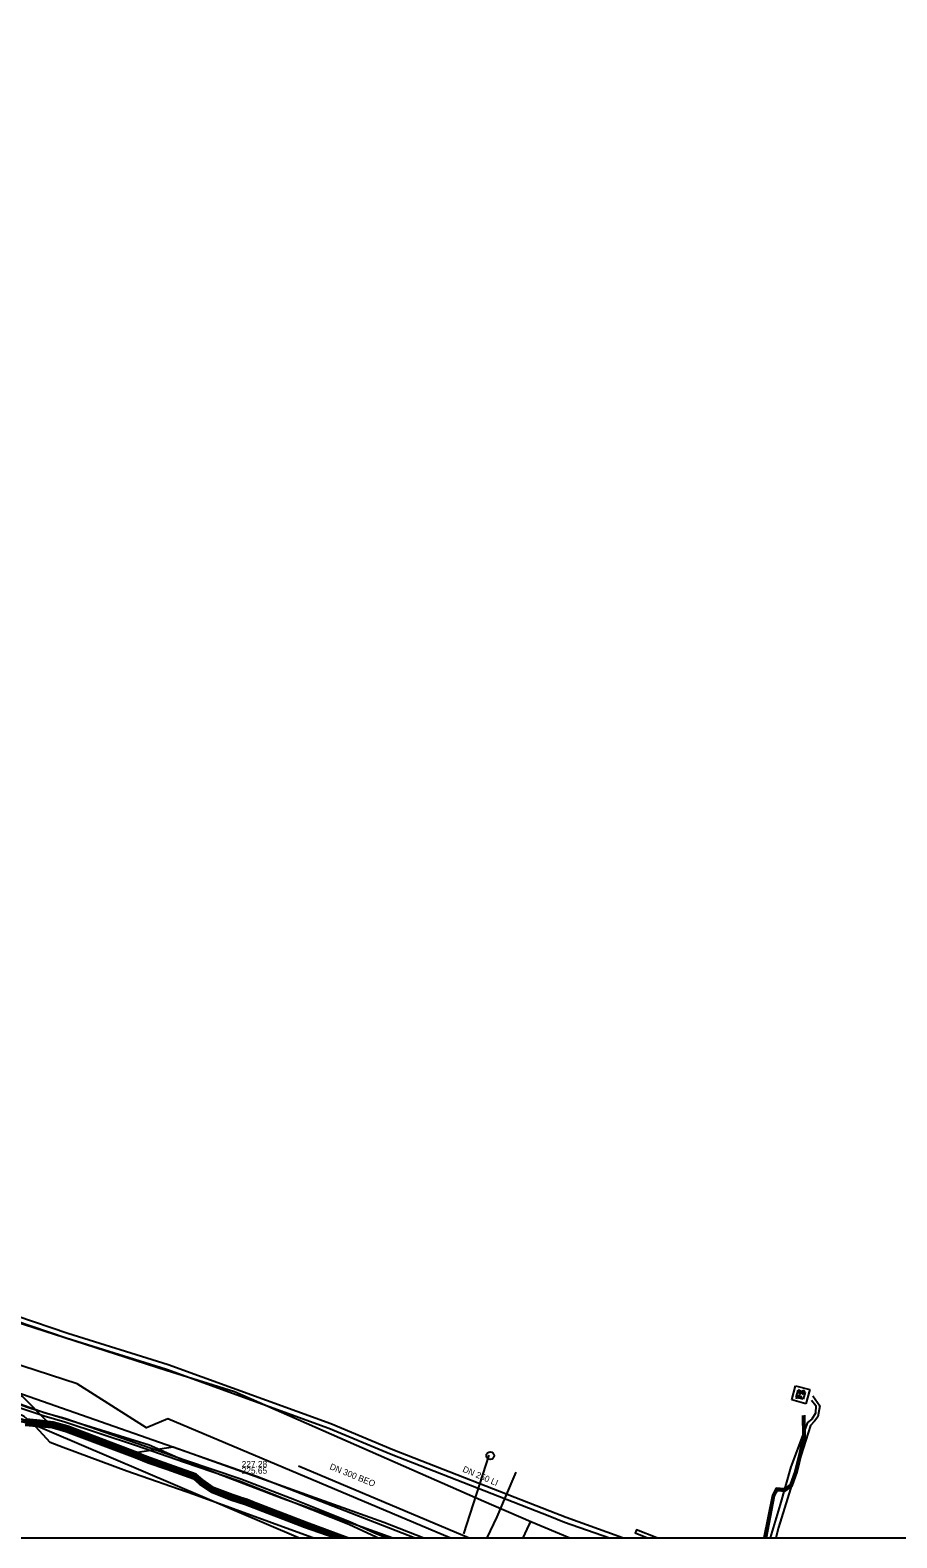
# Model space of a CAD drawing. Extents: x -599951 to -598963, y -1164095 to -1162939.
# Drawn here: x -599566.7 to -599455.4, y -1164094.7 to -1163901.1 of the extents above; entities that cross this region are included whole.
import ezdxf

# ---------------------------------------------------------------- set-up
doc = ezdxf.new("R2010")
doc.units = 0
for name, color, linetype in [('25', 7, 'Continuous'), ('Vrstva 11', 7, 'Continuous'), ('Vrstva 12', 7, 'Continuous'), ('Vrstva 13', 7, 'Continuous'), ('Vrstva 15', 7, 'Continuous'), ('Vrstva 16', 7, 'Continuous'), ('Vrstva 19', 7, 'Continuous'), ('Vrstva 3', 7, 'Continuous'), ('Vrstva 42', 7, 'Continuous'), ('Vrstva 43', 7, 'Continuous'), ('Vrstva 44', 7, 'Continuous'), ('Vrstva 45', 7, 'Continuous'), ('Vrstva 53', 7, 'Continuous'), ('Vrstva 55', 7, 'Continuous'), ('Vrstva 58', 7, 'Continuous'), ('Vrstva 9', 7, 'Continuous')]:
    doc.layers.add(name, color=color, linetype=linetype)

# ---------------------------------------------------------------- blocks, each defined once
blk = doc.blocks.new('VN640')
at = {"layer": '25'}
for points in [[(-1.89, 1.889), (1.889, 1.889)], [(-1.89, -1.89), (-1.89, 1.889)], [(-1.26, 0.787), (-0.221, 0.787)], [(-0.725, 0.787), (-0.725, -0.788)], [(1.197, 0.661), (0.945, 0.787), (0.661, 0.787), (0.409, 0.661), (0.283, 0.472), (0.283, 0.409), (0.409, 0.22), (1.133, -0.158), (1.259, -0.316), (1.259, -0.473), (1.133, -0.662), (0.913, -0.788), (0.629, -0.788), (0.503, -0.725), (0.283, -0.599)], [(1.889, 1.889), (1.889, -1.89)], [(1.889, -1.89), (-1.89, -1.89)]]:
    blk.add_lwpolyline(points, dxfattribs=at)
blk = doc.blocks.new('NN640')
at = {"layer": '25'}
for points in [[(-1.89, 1.889), (1.889, 1.889)], [(-1.89, -1.89), (-1.89, 1.889)], [(-1.26, 0.787), (-0.221, 0.787)], [(-0.725, 0.787), (-0.725, -0.788)], [(1.197, 0.661), (0.945, 0.787), (0.661, 0.787), (0.409, 0.661), (0.283, 0.472), (0.283, 0.409), (0.409, 0.22), (1.133, -0.158), (1.259, -0.316), (1.259, -0.473), (1.133, -0.662), (0.913, -0.788), (0.629, -0.788), (0.503, -0.725), (0.283, -0.599)], [(1.889, 1.889), (1.889, -1.89)], [(1.889, -1.89), (-1.89, -1.89)]]:
    blk.add_lwpolyline(points, dxfattribs=at)

msp = doc.modelspace()

# ---------------------------------------------------------------- linework, layer by layer
at = {"layer": 'Vrstva 11'}
msp.add_circle((-599507.63, -1164084.14), 0.5, dxfattribs=at)
at = {"layer": 'Vrstva 12'}
for points in [[(-599613.46, -1164062.85), (-599613.16, -1164063.2), (-599611.72, -1164063.65), (-599602.03, -1164066.71), (-599599.57, -1164067.42), (-599595.65, -1164068.31), (-599580.24, -1164073.43), (-599577.04, -1164074.47), (-599566.64, -1164078.04), (-599562.59, -1164079.3), (-599551.43, -1164082.77), (-599546.18, -1164085.05), (-599534.35, -1164089.62), (-599520.153, -1164094.695)], [(-599512.817, -1164094.695), (-599549.011, -1164079.426), (-599551.753, -1164080.567), (-599560.66, -1164074.929), (-599578.175, -1164069.238), (-599581.79, -1164068.099), (-599587.439, -1164066.331), (-599595.493, -1164065.607), (-599599.144, -1164064.549), (-599601.105, -1164063.983), (-599607.16, -1164088.185), (-599608.496, -1164094.695)], [(-599565.95, -1164080.45), (-599567.47, -1164079.13), (-599569.21, -1164078.29), (-599577.43, -1164075.58), (-599580.28, -1164074.63), (-599581.54, -1164074.23)], [(-599530.396, -1164094.695), (-599531, -1164094.48), (-599545.67, -1164089.14), (-599554.28, -1164086.13), (-599562.44, -1164083.09), (-599564.11, -1164082.45), (-599565.95, -1164080.45)]]:
    msp.add_lwpolyline(points, dxfattribs=at)
at = {"layer": 'Vrstva 13'}
for points in [[(-599607.67, -1164054.96), (-599590.92, -1164059.94), (-599589.853, -1164060.27), (-599573.8, -1164065.2), (-599570.07, -1164066.42), (-599549.24, -1164073.15), (-599540.472, -1164075.88), (-599508.435, -1164089.969), (-599502.44, -1164092.61), (-599497.429, -1164094.695)], [(-599502.44, -1164092.61), (-599502.68, -1164093.04), (-599503.463, -1164094.695)]]:
    msp.add_lwpolyline(points, dxfattribs=at)
at = {"layer": 'Vrstva 16'}
msp.add_lwpolyline([(-599532.23, -1164094.695), (-599576.26, -1164075.92), (-599581.33, -1164074.29), (-599595.84, -1164069.64), (-599596.96, -1164069.28), (-599602.44, -1164067.76), (-599618.73, -1164062.85), (-599666.38, -1164048.5), (-599672.28, -1164046.86), (-599687.99, -1164042.5)], dxfattribs=at)
at = {"layer": 'Vrstva 19'}
for points in [[(-599517.408, -1164094.695), (-599537.5, -1164086.87), (-599571.84, -1164074.84), (-599589.93, -1164069.71), (-599590.38, -1164069.57), (-599590.89, -1164069.41), (-599601.93, -1164066.13), (-599608.97, -1164063.96), (-599646.01, -1164052.54), (-599646.71, -1164052.33), (-599646.97, -1164052.25), (-599649.244, -1164051.504), (-599665.68, -1164046.42), (-599687.59, -1164039.86)], [(-599508.01, -1164094.695), (-599506.76, -1164092), (-599505.665, -1164089.453), (-599504.3, -1164086.28)]]:
    msp.add_lwpolyline(points, dxfattribs=at)
at = {"layer": 'Vrstva 3'}
for points in [[(-599492.33, -1164094.695), (-599491.183, -1164094.695), (-599491.12, -1164094.53), (-599497.905, -1164092.099), (-599500, -1164091.28), (-599520.117, -1164083.412), (-599528.111, -1164080.071), (-599548.984, -1164072.466), (-599561.867, -1164068.455), (-599581.544, -1164061.776), (-599581.64, -1164062.06), (-599581.735, -1164062.342), (-599562.053, -1164069.025), (-599549.176, -1164073.034), (-599528.329, -1164080.629), (-599520.343, -1164083.968), (-599500, -1164091.924), (-599498.115, -1164092.661)], [(-599491.183, -1164094.695), (-599490.673, -1164094.695), (-599491.12, -1164094.53)], [(-599487.453, -1164094.695), (-599486.245, -1164094.695), (-599488.846, -1164093.651), (-599488.93, -1164093.86), (-599489.01, -1164094.07)]]:
    msp.add_lwpolyline(points, close=True, dxfattribs=at)
at = {"layer": 'Vrstva 42'}
for points in [[(-599526.966, -1164094.695), (-599531.336, -1164093.093), (-599538.889, -1164089.976), (-599543.516, -1164088.57), (-599545.077, -1164087.383), (-599546.233, -1164086.671), (-599549.427, -1164085.563), (-599553.029, -1164083.932), (-599561.911, -1164080.525), (-599563.749, -1164080.019), (-599565.43, -1164079.839), (-599567.196, -1164079.669)], [(-599526.386, -1164094.695), (-599531.264, -1164092.907), (-599538.831, -1164089.784), (-599543.424, -1164088.39), (-599544.963, -1164087.217), (-599546.147, -1164086.489), (-599549.353, -1164085.377), (-599552.951, -1164083.748), (-599561.849, -1164080.335), (-599563.711, -1164079.821), (-599565.41, -1164079.64), (-599567.164, -1164079.471)]]:
    msp.add_lwpolyline(points, dxfattribs=at)
at = {"layer": 'Vrstva 44'}
for points in [[(-599548.889, -1164085.258), (-599551.295, -1164084.429), (-599552.972, -1164083.76), (-599561.884, -1164080.426), (-599563.723, -1164079.874), (-599567.224, -1164079.573), (-599569.544, -1164079.052), (-599572.083, -1164078.09), (-599575.977, -1164076.588), (-599581.178, -1164074.784), (-599584.429, -1164073.814), (-599594.158, -1164070.534), (-599594.617, -1164070.415), (-599595.31, -1164069.65), (-599595.524, -1164069.061), (-599595.504, -1164068.88), (-599595.044, -1164067.4)], [(-599520.995, -1164094.695), (-599522.17, -1164094.21), (-599525.69, -1164092.63), (-599532.76, -1164089.83), (-599539.63, -1164087.15), (-599546.86, -1164084.73), (-599552.99, -1164082.57), (-599562.25, -1164079.36), (-599564.77, -1164078.7), (-599569.35, -1164077.07), (-599576.12, -1164075.03), (-599582.45, -1164072.98), (-599589.38, -1164070.73), (-599593.46, -1164069.48), (-599593.99, -1164069.3)], [(-599594.25, -1164070.82), (-599584.52, -1164074.1), (-599581.27, -1164075.07), (-599576.08, -1164076.87), (-599572.19, -1164078.37), (-599569.63, -1164079.34), (-599567.27, -1164079.87), (-599563.78, -1164080.17), (-599561.98, -1164080.71), (-599553.08, -1164084.04), (-599551.4, -1164084.71), (-599548.99, -1164085.54)], [(-599569.51, -1164077.47), (-599564.88, -1164079.03), (-599562.25, -1164079.78), (-599553.15, -1164082.78), (-599546.89, -1164084.97), (-599539.84, -1164087.37), (-599532.81, -1164090.15), (-599525.79, -1164092.95), (-599522.29, -1164094.58), (-599522.023, -1164094.695)], [(-599466.388, -1164077.007), (-599465.82, -1164077.71), (-599465.889, -1164078.694), (-599466.338, -1164079.45), (-599466.927, -1164079.898), (-599469.05, -1164085.58), (-599470.42, -1164090.41), (-599471.682, -1164094.695)], [(-599466.236, -1164076.474), (-599465.32, -1164077.72), (-599465.59, -1164079.15), (-599465.993, -1164079.709), (-599466.51, -1164080.26), (-599468.31, -1164085.93), (-599470.65, -1164093.35), (-599470.963, -1164094.695)], [(-599567.255, -1164079.771), (-599563.761, -1164080.071), (-599561.948, -1164080.615), (-599553.044, -1164083.947), (-599551.365, -1164084.616), (-599548.956, -1164085.446), (-599545.49, -1164086.712), (-599544.65, -1164087.39), (-599543.143, -1164088.441), (-599540.756, -1164089.366), (-599538.854, -1164089.987)], [(-599467.45, -1164078.961), (-599467.42, -1164081.661), (-599467.838, -1164083.748), (-599468.436, -1164086.191), (-599469.064, -1164087.918), (-599469.82, -1164088.488), (-599470.867, -1164088.416), (-599471.315, -1164089.246), (-599472.39, -1164094.695)], [(-599472.187, -1164094.695), (-599471.125, -1164089.314), (-599470.753, -1164088.624), (-599469.76, -1164088.692), (-599468.896, -1164088.042), (-599468.244, -1164086.249), (-599467.642, -1164083.792), (-599467.22, -1164081.679), (-599467.25, -1164078.959)], [(-599545.643, -1164087.082), (-599549.088, -1164085.824), (-599551.504, -1164084.991), (-599553.188, -1164084.32), (-599562.076, -1164080.994), (-599563.837, -1164080.466), (-599567.316, -1164080.167)], [(-599567.285, -1164079.969), (-599563.799, -1164080.269), (-599562.012, -1164080.805), (-599553.116, -1164084.133), (-599551.435, -1164084.804), (-599549.023, -1164085.635)], [(-599549.023, -1164085.635), (-599545.59, -1164086.888), (-599544.77, -1164087.55), (-599543.237, -1164088.619), (-599540.824, -1164089.554), (-599538.921, -1164090.175), (-599531.375, -1164093.094), (-599527.067, -1164094.695)], [(-599548.99, -1164085.54), (-599545.54, -1164086.8), (-599544.71, -1164087.47), (-599543.19, -1164088.53), (-599540.79, -1164089.46), (-599538.89, -1164090.08)], [(-599525.919, -1164094.695), (-599531.234, -1164092.72), (-599538.782, -1164089.8), (-599540.689, -1164089.177), (-599543.048, -1164088.263), (-599544.53, -1164087.23), (-599545.39, -1164086.535), (-599548.889, -1164085.258)], [(-599527.641, -1164094.695), (-599531.446, -1164093.281), (-599538.991, -1164090.363), (-599540.891, -1164089.743), (-599543.332, -1164088.797), (-599544.89, -1164087.71), (-599545.643, -1164087.082)], [(-599538.89, -1164090.08), (-599531.34, -1164093), (-599526.779, -1164094.695)], [(-599538.854, -1164089.987), (-599531.305, -1164092.907), (-599526.493, -1164094.695)]]:
    msp.add_lwpolyline(points, dxfattribs=at)
at = {"layer": 'Vrstva 53'}
msp.add_lwpolyline([(-599951.125, -1164094.695), (-598963.215, -1164094.695), (-598963.215, -1162939.4), (-599951.125, -1162939.4)], close=True, dxfattribs=at)
at = {"layer": 'Vrstva 55'}
msp.add_lwpolyline([(-599730.225, -1164030.406), (-599699.561, -1164039.03), (-599699.101, -1164037.918), (-599699.561, -1164039.03), (-599667.715, -1164049.284), (-599667.086, -1164049.415), (-599666.671, -1164048.038), (-599667.086, -1164049.415), (-599641.77, -1164056.83), (-599641.359, -1164055.754), (-599641.77, -1164056.83), (-599613.23, -1164064.88), (-599603.95, -1164067.14), (-599599.17, -1164066.34), (-599581.67, -1164071.86), (-599567.7, -1164076.51), (-599564.49, -1164079.74), (-599552.92, -1164083.71), (-599548.31, -1164083.01), (-599521.3, -1164092.7), (-599516.137, -1164094.695)], dxfattribs=at)
at = {"layer": 'Vrstva 58'}
for points in [[(-599525.905, -1164094.695), (-599530.24, -1164093.195), (-599531.269, -1164092.813), (-599538.824, -1164089.891), (-599540.723, -1164089.272), (-599543.095, -1164088.352), (-599544.59, -1164087.31), (-599545.44, -1164086.624), (-599548.922, -1164085.352), (-599551.33, -1164084.522), (-599553.008, -1164083.853), (-599561.916, -1164080.52), (-599563.742, -1164079.972), (-599567.239, -1164079.672)], [(-599467.55, -1164078.962), (-599467.52, -1164081.651), (-599467.935, -1164083.727), (-599468.532, -1164086.162), (-599469.148, -1164087.856), (-599469.851, -1164088.385), (-599470.925, -1164088.312), (-599471.41, -1164089.212), (-599472.493, -1164094.695)], [(-599472.289, -1164094.695), (-599471.22, -1164089.28), (-599470.81, -1164088.52), (-599469.79, -1164088.59), (-599468.98, -1164087.98), (-599468.34, -1164086.22), (-599467.74, -1164083.77), (-599467.32, -1164081.67), (-599467.35, -1164078.96)], [(-599527.673, -1164094.695), (-599531.482, -1164093.374), (-599539.024, -1164090.457), (-599540.924, -1164089.837), (-599543.379, -1164088.886), (-599544.951, -1164087.79), (-599545.694, -1164087.17), (-599549.121, -1164085.918), (-599551.539, -1164085.085), (-599553.224, -1164084.413), (-599562.108, -1164081.089), (-599563.855, -1164080.565), (-599567.331, -1164080.266)], [(-599567.301, -1164080.068), (-599563.818, -1164080.367), (-599562.044, -1164080.9), (-599553.152, -1164084.227), (-599551.47, -1164084.898), (-599549.057, -1164085.728), (-599545.64, -1164086.976), (-599544.83, -1164087.63), (-599543.285, -1164088.708), (-599540.857, -1164089.648), (-599538.957, -1164090.268), (-599531.409, -1164093.188), (-599527.077, -1164094.695)], [(-599567.27, -1164079.87), (-599563.78, -1164080.17), (-599561.98, -1164080.71), (-599553.08, -1164084.04), (-599551.4, -1164084.71), (-599548.99, -1164085.54), (-599545.54, -1164086.8), (-599544.71, -1164087.47), (-599543.19, -1164088.53), (-599540.79, -1164089.46), (-599538.89, -1164090.08), (-599531.34, -1164093), (-599526.468, -1164094.695)]]:
    msp.add_lwpolyline(points, dxfattribs=at)
at = {"layer": 'Vrstva 9'}
for p, q in [((-599532.247, -1164085.445), (-599510.334, -1164094.695)), ((-599511.04, -1164094.18), (-599507.76, -1164084.09))]:
    msp.add_line(p, q, dxfattribs=at)

# ---------------------------------------------------------------- block references
at = {"layer": 'Vrstva 43', "xscale": 0.5, "yscale": 0.5000000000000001, "rotation": 75}
msp.add_blockref('NN640', (-599467.782, -1164076.322), dxfattribs=at)
at = {"layer": 'Vrstva 45', "xscale": 0.24999999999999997, "yscale": 0.25000000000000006, "rotation": 75}
msp.add_blockref('VN640', (-599467.782, -1164076.322), dxfattribs=at)

# ---------------------------------------------------------------- texts
at = {"layer": 'Vrstva 12'}
for s, p in [('227.28', (-599539.534, -1164085.618)), ('225.65', (-599539.534, -1164086.45))]:
    msp.add_text(s, height=0.8, dxfattribs=at).set_placement(p)
msp.add_text('DN 300 BEO', height=0.8, rotation=338.03174, dxfattribs=at).set_placement((-599528.314, -1164085.849))
at = {"layer": 'Vrstva 15'}
msp.add_text('DN 250 LI', height=0.8, rotation=336.89918, dxfattribs=at).set_placement((-599511.255, -1164086.171))

doc.saveas('drawing.dxf')
